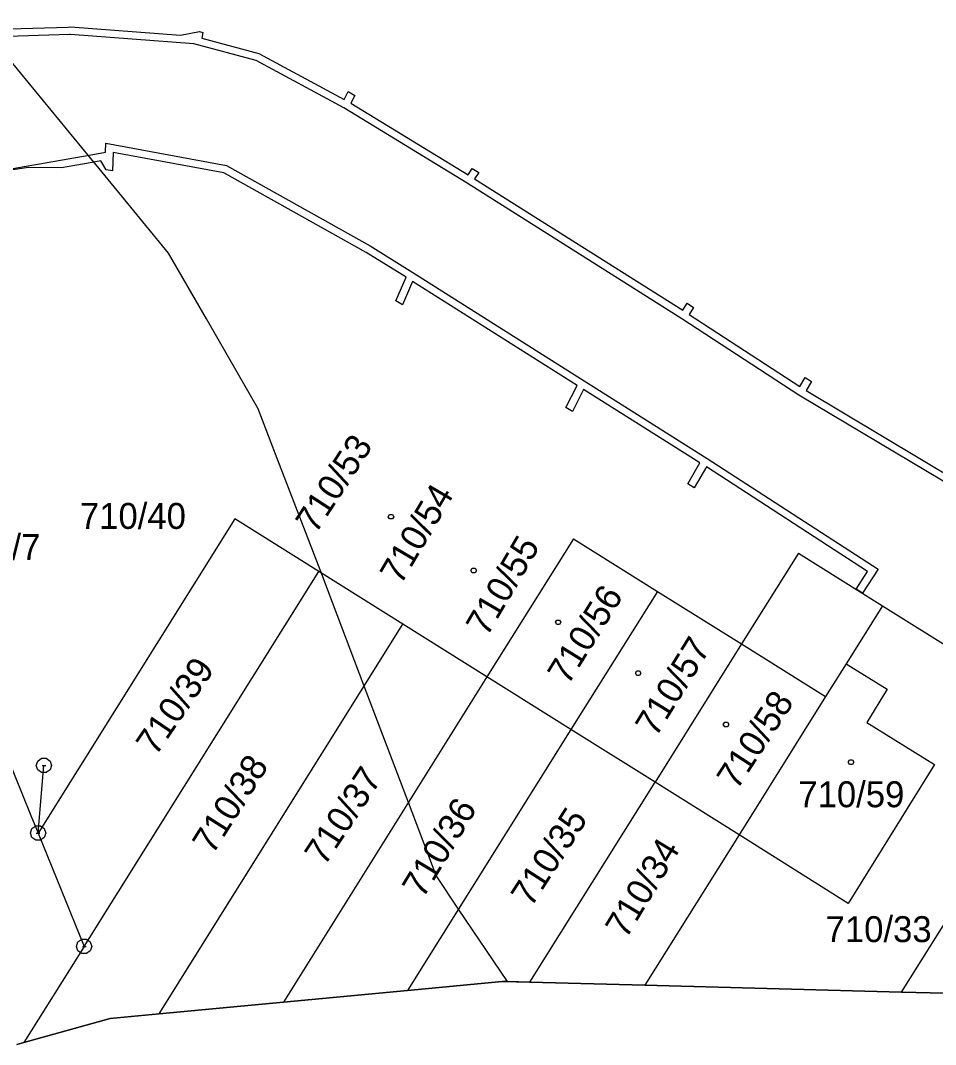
# Model space of a CAD drawing. Extents: x -759699 to -757730, y -1172308 to -1170857.
# Drawn here: x -757903.5 to -757843.5, y -1171040.2 to -1170973.1 of the extents above; entities that cross this region are included whole.
import ezdxf

# ---------------------------------------------------------------- set-up
doc = ezdxf.new("R2010")
doc.units = 0
for name, color, linetype in [('Vrstva 1', 7, 'Continuous'), ('Vrstva 11', 7, 'Continuous'), ('Vrstva 12', 7, 'Continuous'), ('Vrstva 13', 7, 'Continuous'), ('Vrstva 2', 7, 'Continuous'), ('Vrstva 4', 7, 'Continuous'), ('Vrstva 5', 7, 'Continuous'), ('Vrstva 8', 7, 'Continuous')]:
    doc.layers.add(name, color=color, linetype=linetype)

msp = doc.modelspace()

# ---------------------------------------------------------------- linework, layer by layer
at = {"layer": 'Vrstva 1'}
for p, q in [((-757911.47, -1171003.78), (-757902.77, -1171025.17)), ((-757889.4, -1171005.74), (-757902.3, -1171026.33)), ((-757889.4, -1171005.74), (-757889.4, -1171005.74)), ((-757889.4, -1171005.74), (-757889.4, -1171005.74)), ((-757883.89, -1171009.19), (-757889.4, -1171005.74)), ((-757867.2, -1171007.05), (-757872.87, -1171016.09)), ((-757867.2, -1171007.05), (-757867.2, -1171007.05)), ((-757852.45, -1171007.98), (-757856.18, -1171013.93)), ((-757852.45, -1171007.98), (-757852.45, -1171007.98)), ((-757852.45, -1171007.98), (-757846.94, -1171011.43)), ((-757899.28, -1171033.76), (-757883.89, -1171009.19)), ((-757883.89, -1171009.19), (-757883.89, -1171009.19)), ((-757878.38, -1171012.64), (-757883.89, -1171009.19)), ((-757861.69, -1171010.49), (-757867.36, -1171019.54)), ((-757861.69, -1171010.49), (-757861.69, -1171010.49)), ((-757846.94, -1171011.43), (-757849.32, -1171015.23)), ((-757846.94, -1171011.43), (-757834.65, -1171019.13)), ((-757894.37, -1171038.17), (-757878.38, -1171012.64)), ((-757878.38, -1171012.64), (-757878.38, -1171012.64)), ((-757872.87, -1171016.09), (-757878.38, -1171012.64)), ((-757856.18, -1171013.93), (-757861.85, -1171022.99)), ((-757849.32, -1171015.23), (-757850.66, -1171017.37)), ((-757849.32, -1171015.23), (-757846.62, -1171016.9)), ((-757872.87, -1171016.09), (-757886.22, -1171037.4)), ((-757867.36, -1171019.54), (-757872.87, -1171016.09)), ((-757846.62, -1171016.9), (-757847.97, -1171019.07)), ((-757850.66, -1171017.37), (-757856.34, -1171026.44)), ((-757847.97, -1171019.07), (-757843.53, -1171021.83)), ((-757845.69, -1171036.74), (-757834.65, -1171019.13)), ((-757867.36, -1171019.54), (-757878.07, -1171036.63)), ((-757861.85, -1171022.99), (-757867.36, -1171019.54)), ((-757843.53, -1171021.83), (-757849.18, -1171030.93)), ((-757902.3, -1171026.33), (-757901.92, -1171021.9)), ((-757901.92, -1171021.9), (-757901.92, -1171021.9)), ((-757870.06, -1171036.1), (-757861.85, -1171022.99)), ((-757856.34, -1171026.44), (-757861.85, -1171022.99)), ((-757902.77, -1171025.17), (-757902.3, -1171026.33)), ((-757902.3, -1171026.33), (-757899.28, -1171033.76)), ((-757856.34, -1171026.44), (-757862.52, -1171036.3)), ((-757849.18, -1171030.93), (-757856.34, -1171026.44)), ((-757899.28, -1171033.76), (-757903.23, -1171040.05)), ((-757878.07, -1171036.63), (-757871.88, -1171036.05)), ((-757871.88, -1171036.05), (-757870.06, -1171036.1)), ((-757870.06, -1171036.1), (-757862.52, -1171036.3)), ((-757862.52, -1171036.3), (-757845.69, -1171036.74)), ((-757886.22, -1171037.4), (-757878.07, -1171036.63)), ((-757845.69, -1171036.74), (-757838.3, -1171036.94)), ((-757894.37, -1171038.17), (-757886.22, -1171037.4)), ((-757903.23, -1171040.05), (-757897.57, -1171038.47)), ((-757897.57, -1171038.47), (-757894.37, -1171038.17)), ((-757903.69, -1171040.18), (-757903.23, -1171040.05))]:
    msp.add_line(p, q, dxfattribs=at)
at = {"layer": 'Vrstva 11'}
for p, q in [((-757898.94, -1170982), (-757906.28, -1170973.07)), ((-757898.3, -1170982.77), (-757898.94, -1170982)), ((-757893.75, -1170988.31), (-757898.3, -1170982.77)), ((-757891.27, -1170992.62), (-757893.75, -1170988.31)), ((-757887.88, -1170998.52), (-757891.27, -1170992.62)), ((-757886.74, -1171001.49), (-757887.88, -1170998.52)), ((-757883.81, -1171009.07), (-757886.74, -1171001.49)), ((-757883.73, -1171009.29), (-757883.81, -1171009.07)), ((-757883.3, -1171010.41), (-757883.73, -1171009.29)), ((-757880.92, -1171016.69), (-757883.3, -1171010.41)), ((-757878.02, -1171024.32), (-757880.92, -1171016.69)), ((-757876.21, -1171029.11), (-757878.02, -1171024.32)), ((-757874.73, -1171031.3), (-757876.21, -1171029.11)), ((-757871.53, -1171036.06), (-757874.73, -1171031.3)), ((-757871.88, -1171036.05), (-757878.07, -1171036.63)), ((-757871.53, -1171036.06), (-757871.88, -1171036.05)), ((-757870.06, -1171036.1), (-757871.53, -1171036.06)), ((-757862.52, -1171036.3), (-757870.06, -1171036.1)), ((-757845.69, -1171036.74), (-757862.52, -1171036.3)), ((-757878.07, -1171036.63), (-757886.22, -1171037.4)), ((-757838.3, -1171036.94), (-757845.69, -1171036.74)), ((-757886.22, -1171037.4), (-757894.37, -1171038.17)), ((-757897.57, -1171038.47), (-757903.23, -1171040.05)), ((-757894.37, -1171038.17), (-757897.57, -1171038.47)), ((-757903.23, -1171040.05), (-757903.69, -1171040.18))]:
    msp.add_line(p, q, dxfattribs=at)
at = {"layer": 'Vrstva 12'}
for p, q in [((-757889.4, -1171005.74), (-757889.4, -1171005.74)), ((-757889.4, -1171005.74), (-757889.4, -1171005.74)), ((-757883.89, -1171009.19), (-757889.4, -1171005.74)), ((-757889.4, -1171005.74), (-757889.4, -1171005.74)), ((-757867.2, -1171007.05), (-757872.87, -1171016.09)), ((-757867.2, -1171007.05), (-757872.87, -1171016.09)), ((-757867.2, -1171007.05), (-757867.2, -1171007.05)), ((-757867.2, -1171007.05), (-757861.69, -1171010.49)), ((-757883.89, -1171009.19), (-757883.89, -1171009.19)), ((-757883.89, -1171009.19), (-757883.89, -1171009.19)), ((-757878.38, -1171012.64), (-757883.89, -1171009.19)), ((-757861.69, -1171010.49), (-757867.36, -1171019.54)), ((-757861.69, -1171010.49), (-757867.36, -1171019.54)), ((-757861.69, -1171010.49), (-757856.18, -1171013.93)), ((-757878.38, -1171012.64), (-757878.38, -1171012.64)), ((-757878.38, -1171012.64), (-757878.38, -1171012.64)), ((-757872.87, -1171016.09), (-757878.38, -1171012.64)), ((-757856.18, -1171013.93), (-757861.85, -1171022.99)), ((-757856.18, -1171013.93), (-757861.85, -1171022.99)), ((-757856.18, -1171013.93), (-757850.66, -1171017.37)), ((-757849.32, -1171015.23), (-757850.66, -1171017.37)), ((-757849.32, -1171015.23), (-757846.62, -1171016.9)), ((-757867.36, -1171019.54), (-757872.87, -1171016.09)), ((-757846.62, -1171016.9), (-757847.97, -1171019.07)), ((-757850.66, -1171017.37), (-757856.34, -1171026.44)), ((-757850.66, -1171017.37), (-757856.34, -1171026.44)), ((-757847.97, -1171019.07), (-757843.53, -1171021.83)), ((-757861.85, -1171022.99), (-757867.36, -1171019.54)), ((-757843.53, -1171021.83), (-757849.18, -1171030.93)), ((-757856.34, -1171026.44), (-757861.85, -1171022.99)), ((-757849.18, -1171030.93), (-757856.34, -1171026.44))]:
    msp.add_line(p, q, dxfattribs=at)
at = {"layer": 'Vrstva 13'}
for p, q in [((-757907.79, -1170973.72), (-757900.34, -1170973.5)), ((-757900.34, -1170973.5), (-757900.17, -1170973.49)), ((-757900.17, -1170973.49), (-757892.96, -1170974.04)), ((-757900.25, -1170973.99), (-757907.9, -1170974.22)), ((-757900.19, -1170973.99), (-757900.25, -1170973.99)), ((-757892.1, -1170974.6), (-757900.19, -1170973.99)), ((-757892.96, -1170974.04), (-757891.72, -1170973.79)), ((-757891.72, -1170973.79), (-757891.51, -1170973.85)), ((-757891.51, -1170973.85), (-757891.56, -1170974.22)), ((-757888.01, -1170975.7), (-757892.1, -1170974.6)), ((-757891.56, -1170974.22), (-757887.83, -1170975.24)), ((-757887.83, -1170975.24), (-757882.24, -1170978.24)), ((-757882.25, -1170978.8), (-757888.01, -1170975.7)), ((-757882.24, -1170978.24), (-757881.98, -1170977.73)), ((-757881.98, -1170977.73), (-757881.54, -1170977.99)), ((-757881.54, -1170977.99), (-757881.8, -1170978.49)), ((-757874.16, -1170983.73), (-757882.25, -1170978.8)), ((-757881.8, -1170978.49), (-757874.11, -1170983.18)), ((-757897.89, -1170981.71), (-757897.87, -1170981.12)), ((-757897.87, -1170981.12), (-757889.95, -1170982.58)), ((-757913.28, -1170984.39), (-757898.96, -1170981.9)), ((-757898.96, -1170981.9), (-757897.89, -1170981.71)), ((-757897.39, -1170981.72), (-757897.42, -1170982.92)), ((-757890.13, -1170983.06), (-757897.39, -1170981.72)), ((-757902.93, -1170982.7), (-757907.3, -1170983.37)), ((-757900.78, -1170982.72), (-757902.93, -1170982.7)), ((-757898.88, -1170982.39), (-757900.78, -1170982.72)), ((-757898.18, -1170982.27), (-757898.88, -1170982.39)), ((-757897.85, -1170982.85), (-757898.18, -1170982.27)), ((-757897.42, -1170982.92), (-757897.85, -1170982.85)), ((-757889.95, -1170982.58), (-757880.53, -1170987.83)), ((-757874.11, -1170983.18), (-757873.84, -1170982.77)), ((-757873.84, -1170982.77), (-757873.41, -1170983.04)), ((-757880.79, -1170988.27), (-757890.13, -1170983.06)), ((-757873.41, -1170983.04), (-757873.68, -1170983.45)), ((-757873.68, -1170983.45), (-757860.03, -1170992.06)), ((-757860.09, -1170992.62), (-757874.16, -1170983.73)), ((-757878.17, -1170989.9), (-757880.79, -1170988.27)), ((-757880.53, -1170987.83), (-757877.73, -1170989.59)), ((-757877.73, -1170989.59), (-757866.5, -1170996.69)), ((-757878.84, -1170991.44), (-757878.17, -1170989.9)), ((-757877.75, -1170990.17), (-757878.41, -1170991.71)), ((-757866.96, -1170996.99), (-757877.75, -1170990.17)), ((-757878.41, -1170991.71), (-757878.84, -1170991.44)), ((-757860.03, -1170992.06), (-757859.75, -1170991.6)), ((-757859.75, -1170991.6), (-757859.33, -1170991.87)), ((-757859.33, -1170991.87), (-757859.61, -1170992.33)), ((-757852.41, -1170997.62), (-757860.09, -1170992.62)), ((-757859.61, -1170992.33), (-757852.36, -1170997.06)), ((-757867.69, -1170998.43), (-757866.96, -1170996.99)), ((-757866.5, -1170996.69), (-757858.43, -1171001.77)), ((-757852.36, -1170997.06), (-757852, -1170996.46)), ((-757852, -1170996.46), (-757851.58, -1170996.73)), ((-757851.58, -1170996.73), (-757851.94, -1170997.32)), ((-757866.53, -1170997.26), (-757867.26, -1170998.69)), ((-757858.9, -1171002.06), (-757866.53, -1170997.26)), ((-757840.99, -1171004.45), (-757852.41, -1170997.62)), ((-757851.94, -1170997.32), (-757841.13, -1171003.79)), ((-757867.26, -1170998.69), (-757867.69, -1170998.43)), ((-757859.7, -1171003.44), (-757858.9, -1171002.06)), ((-757858.48, -1171002.33), (-757859.28, -1171003.7)), ((-757847.91, -1171009.17), (-757858.48, -1171002.33)), ((-757858.43, -1171001.77), (-757847.21, -1171009.03)), ((-757859.28, -1171003.7), (-757859.7, -1171003.44)), ((-757847.21, -1171009.03), (-757848.25, -1171010.61)), ((-757848.67, -1171010.34), (-757847.91, -1171009.17)), ((-757848.25, -1171010.61), (-757848.67, -1171010.34))]:
    msp.add_line(p, q, dxfattribs=at)
at = {"layer": 'Vrstva 4'}
for p, q in [((-757867.2, -1171007.05), (-757867.2, -1171007.05)), ((-757867.2, -1171007.05), (-757861.69, -1171010.49)), ((-757861.69, -1171010.49), (-757856.18, -1171013.93)), ((-757856.18, -1171013.93), (-757850.66, -1171017.37))]:
    msp.add_line(p, q, dxfattribs=at)
at = {"layer": 'Vrstva 5'}
for points in [[(-757879.07, -1171005.44), (-757878.98, -1171005.59), (-757879.07, -1171005.74), (-757879.25, -1171005.74), (-757879.34, -1171005.59), (-757879.25, -1171005.44)], [(-757873.65, -1171008.96), (-757873.56, -1171009.11), (-757873.65, -1171009.26), (-757873.83, -1171009.26), (-757873.92, -1171009.11), (-757873.83, -1171008.96)], [(-757868.11, -1171012.36), (-757868.02, -1171012.51), (-757868.11, -1171012.66), (-757868.29, -1171012.66), (-757868.38, -1171012.51), (-757868.29, -1171012.36)], [(-757862.86, -1171015.7), (-757862.77, -1171015.85), (-757862.86, -1171016), (-757863.04, -1171016), (-757863.13, -1171015.85), (-757863.04, -1171015.7)], [(-757857.1, -1171019.05), (-757857.01, -1171019.2), (-757857.1, -1171019.35), (-757857.28, -1171019.35), (-757857.37, -1171019.2), (-757857.28, -1171019.05)], [(-757848.91, -1171021.53), (-757848.82, -1171021.68), (-757848.91, -1171021.83), (-757849.09, -1171021.83), (-757849.18, -1171021.68), (-757849.09, -1171021.53)]]:
    msp.add_lwpolyline(points, close=True, dxfattribs=at)
at = {"layer": 'Vrstva 8'}
for p, q in [((-757902.04, -1171021.9), (-757901.8, -1171021.9)), ((-757902.42, -1171026.33), (-757902.18, -1171026.33)), ((-757899.4, -1171033.76), (-757899.16, -1171033.76))]:
    msp.add_line(p, q, dxfattribs=at)
for points in [[(-757901.77, -1171021.42), (-757901.52, -1171021.6), (-757901.42, -1171021.89), (-757901.52, -1171022.18), (-757901.77, -1171022.36), (-757902.08, -1171022.36), (-757902.33, -1171022.18), (-757902.43, -1171021.89), (-757902.33, -1171021.6), (-757902.08, -1171021.42)], [(-757902.15, -1171025.85), (-757901.9, -1171026.03), (-757901.8, -1171026.32), (-757901.9, -1171026.61), (-757902.15, -1171026.79), (-757902.46, -1171026.79), (-757902.71, -1171026.61), (-757902.81, -1171026.32), (-757902.71, -1171026.03), (-757902.46, -1171025.85)], [(-757899.13, -1171033.28), (-757898.88, -1171033.46), (-757898.78, -1171033.75), (-757898.88, -1171034.04), (-757899.13, -1171034.22), (-757899.44, -1171034.22), (-757899.69, -1171034.04), (-757899.79, -1171033.75), (-757899.69, -1171033.46), (-757899.44, -1171033.28)]]:
    msp.add_lwpolyline(points, close=True, dxfattribs=at)

# ---------------------------------------------------------------- texts
at = {"layer": 'Vrstva 2'}
for s, rotation, p in [('710/53', 56.95201, (-757884.101, -1171006.771)), ('710/54', 59.53031, (-757878.52, -1171010.115)), ('710/55', 59.7022, (-757872.87, -1171013.515)), ('710/56', 58.21251, (-757867.555, -1171016.688)), ('710/57', 58.3271, (-757861.795, -1171020.098)), ('710/39', 55.80609, (-757894.587, -1171021.334)), ('710/58', 56.95201, (-757856.481, -1171023.561)), ('710/38', 57.75414, (-757890.853, -1171027.789)), ('710/37', 56.60823, (-757883.519, -1171028.542)), ('710/36', 58.95736, (-757877.068, -1171030.667)), ('710/35', 57.29578, (-757869.972, -1171031.25)), ('710/34', 58.95736, (-757863.748, -1171033.317))]:
    msp.add_text(s, height=1.7, rotation=rotation, dxfattribs=at).set_placement(p)
for s, p in [('710/40', (-757899.563, -1171006.39)), ('709/7', (-757907.843, -1171008.43)), ('710/59', (-757852.453, -1171024.63)), ('710/33', (-757850.663, -1171033.47))]:
    msp.add_text(s, height=1.7, dxfattribs=at).set_placement(p)

doc.saveas('drawing.dxf')
